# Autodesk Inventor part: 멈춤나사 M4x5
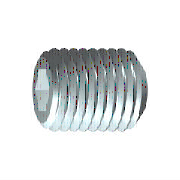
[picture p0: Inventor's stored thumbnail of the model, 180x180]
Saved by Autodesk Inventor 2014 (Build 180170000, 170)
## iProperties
IsCustomPart: 1
Created: 2012-02
Part Number: 멈춤나사 M4x5
Material: 강철, 연강
Description: 6각 소켓 머리 없는 멈춤 나사
Document SubType Name: Modeling
Standard: KS B 1028
Designer: mduedu
Standards Organization: KS
Language: ko-KR
Size Designation: 납작점M4x5
Categories: <MemberInstance><Categories><Category DisplayName="조임쇠" InternalName="e4da775c-781d-43d5-af7c-5136215cf5a6" Mnemonic="FSTN"><Category DisplayName="볼트" InternalN
Density: 1 g/cm^3
Appearance: Steel
Author: mduedu
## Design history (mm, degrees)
sketch "스케치1"
  geometry: L1 (0, 0)-(1.833, 0); L2 (5, 1.155)-(5, 2); L3 (5, 2)-(0, 2); L4 (5, 1.155)-(2.5, 1.155); L5 (2.5, 1.155)-(1.833, 0); L6 (0, -0.4)-(0, 2.4) reference; L7 (0, 2)-(0, 0)
  constraints: 13 end point, 3 parallel, 1 collinear, 1 perpendicular, 1 point on line
  dimensions: "d0" = 2.5 distance of L2.start L4.end (= INTI); "d1" = 60 deg angle of L5 L1; "d2" = 4 diameter of L3 L1 (= NND); "d3" = 2.3094 diameter of L4 L1 (= 1.1547 x SW); "d5" = 5 distance from line of L2 L3.end (= NLG)
revolve "본체" sketch "스케치1" stored, may be unused: angle "d6" = 90 deg
sketch "스케치2"
  geometry: L1 (-0.577, 1)-(0.577, 1); L2 (0.577, 1)-(1.155, 0); L3 (1.155, 0)-(0.577, -1); L4 (0.577, -1)-(-0.577, -1); L5 (-0.577, -1)-(-1.155, 0); L6 (-1.155, 0)-(-0.577, 1); A1 r 1.155 centre (0, 0) between (-0.577, 1) and (0.577, 1) reference; 2 further points
  constraints: 12 end point, 2 point on circle, 1 coincident, 1 horizontal, 11 other
extrude "슬롯" join sketch "스케치2" taper "d9" = 0 deg; stored distance "d21" = 10
workaxis "Work Axis1"
workplane "Work Plane1"
workaxis "Work Axis2"
workpoint "Work Point1"
  workaxis "Work Axis3"
body "Solid1"
chamfer "모따기1" distance "d7" = 0.42941 (= -0.5 x GD1 + 0.5 x NND); stored, may be unused: angle "d8" = 45 deg (= FAWI), second distance "d29" = 0.42941 (= -0.5 x GD1 + 0.5 x NND)
feature "스레드" dims "d11" = 5 (= NLG), "d12" = 0
chamfer "모따기2" distance "d13" = 0.42941 (= -0.5 x GD1 + 0.5 x NND); stored, may be unused: angle "d14" = 45 deg (= FAWI), second distance "d30" = 0.42941 (= -0.5 x GD1 + 0.5 x NND)
other parameters: "NND" = 4 [user parameter; used in 5 equation terms], "NLG" = 5 [user parameter; used in 2 equation terms], "INTI" = 2.5 [user parameter; used in 1 equation term], "FAWI" = 45 deg [user parameter; used in 2 equation terms], "SW" = 2 [user parameter; used in 2 equation terms], "GD1" = 3.14117 (= THREADDIA - 1.2269 x PTC) [user parameter; used in 4 equation terms], "d4" = 0, "FAWI1" = 45 deg [user parameter], "d15" = 0, "d31" = 0, "GUL" = 0.42941 (= 0.61345 x PTC) [user parameter], "SPD" = 2.5 [user parameter], "TPU" = 14.28571 (computed from PTC) [user parameter], "TOA" = 30 deg [user parameter], "THREADDIA" = 4 [user parameter; used in 1 equation term], "PTC" = 0.7 [user parameter; used in 4 equation terms], "GAL" = 0.42941 (= 0.61345 x PTC) [user parameter], "E0" = 2.31 (= 1.155 x SW) [user parameter]
